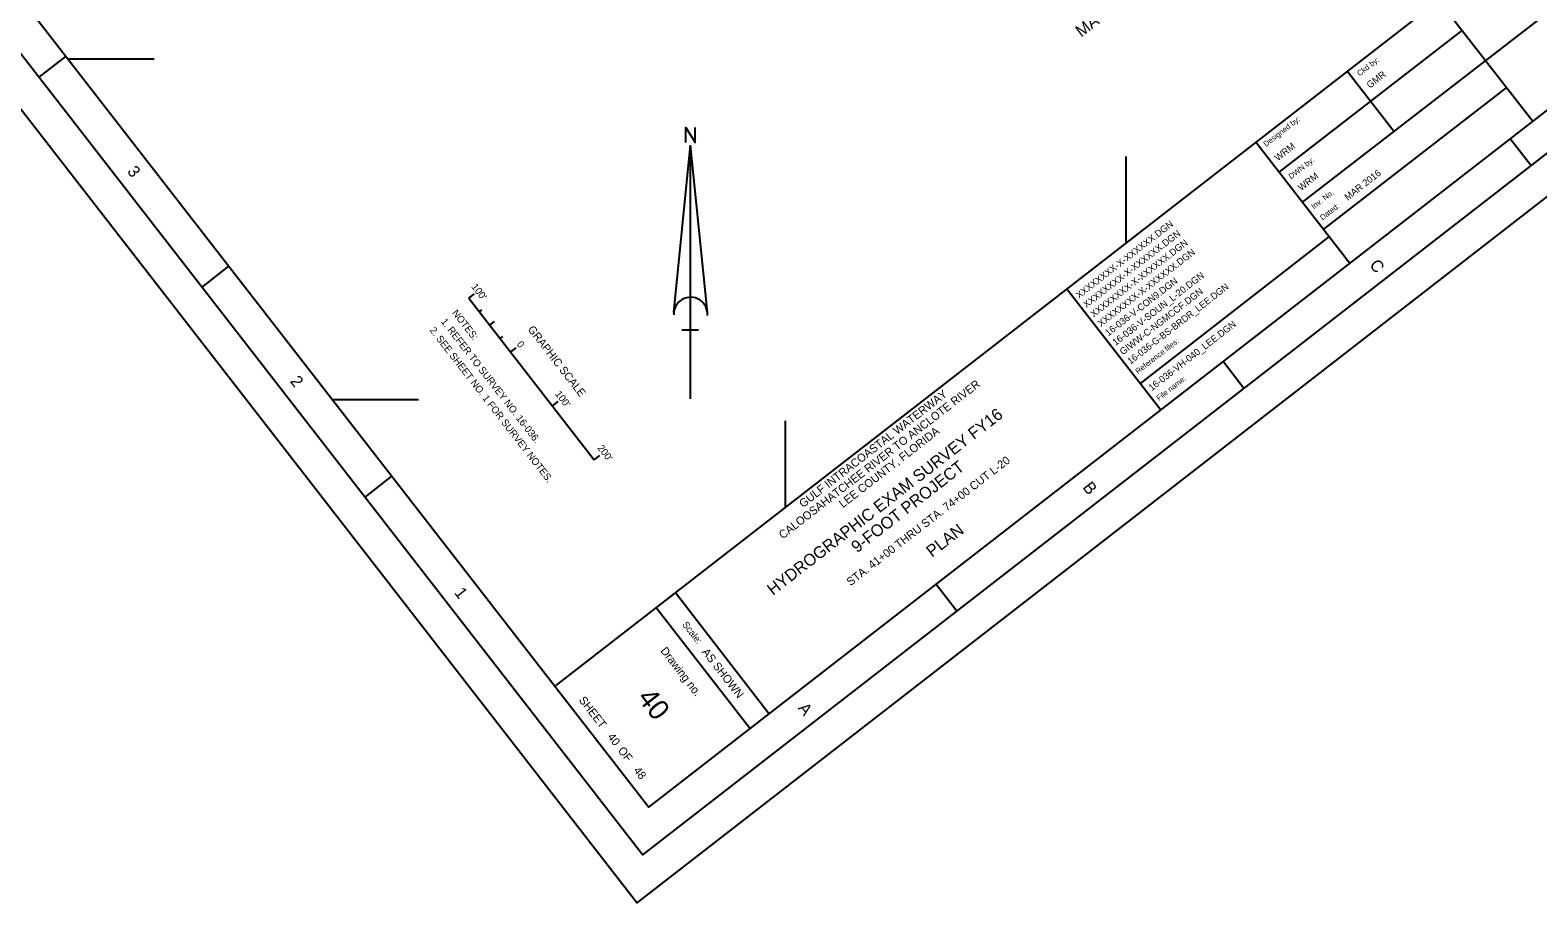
# Model space of a CAD drawing. Extents: x 575584 to 580968, y 857761 to 863322.
# Drawn here: x 577392 to 579604, y 857761 to 859042 of the extents above; entities that cross this region are included whole.
import ezdxf

# ---------------------------------------------------------------- set-up
doc = ezdxf.new("R2010")
doc.units = 0
for name, color, linetype in [('G-ANNO-NPLT', 7, 'Continuous'), ('G-ANNO-TEXT-DRWG', 7, 'Continuous'), ('G-ANNO-TEXT-PROJ', 7, 'Continuous'), ('G-ANNO-TEXT-TTLB', 7, 'Continuous'), ('G-ANNO-TTLB', 7, 'Continuous'), ('V-ANNO-MATC-IDEN', 7, 'Continuous'), ('V-ANNO-NOTE', 7, 'Continuous'), ('V-ANNO-SYMB', 7, 'Continuous'), ('V-TOPO-COOR-STAT', 7, 'Continuous')]:
    doc.layers.add(name, color=color, linetype=linetype)

msp = doc.modelspace()

# ---------------------------------------------------------------- linework, layer by layer
at = {"layer": 'G-ANNO-NPLT'}
msp.add_lwpolyline([(578269.8, 863321.7), (580967.7, 859846), (578281.9, 857761.2), (575584, 861237)], close=True, dxfattribs=at)
msp.add_lwpolyline([(578321.5, 857791.8), (578282, 857761.1), (578251.3, 857800.6)], dxfattribs=at)
at = {"layer": 'G-ANNO-TTLB'}
for p, q in [((580689.4, 860041.4), (578161.6, 858079.3)), ((579258.8, 858789.3), (579938.3, 859315.9)), ((579458.1, 859086.6), (579596.5, 858908.2)), ((579224.6, 858833.6), (579493, 859041.6)), ((577404.7, 858972.8), (577444.2, 859003.5)), ((579323.9, 858982.5), (579393.1, 858893.4)), ((579557.9, 858958), (579289.6, 858749.7)), ((579189.5, 858878.7), (579328.2, 858700)), ((579594.1, 858843), (579563.4, 858882.5)), ((579298, 858738.9), (579020.4, 858523.4)), ((577643.9, 858664.7), (577683.4, 858695.4)), ((578912.7, 858662.2), (579050.6, 858484.5)), ((579172.8, 858516), (579142.1, 858555.5)), ((577883, 858356.7), (577922.5, 858387.3)), ((578751.5, 858189), (578720.9, 858228.5)), ((578338.4, 858216.5), (578476.3, 858038.7)), ((578310.2, 858194.6), (578448.2, 858016.8))]:
    msp.add_line(p, q, dxfattribs=at)
for points in [[(575654.1, 861228.1), (578290.7, 857831.4), (580897.6, 859854.8), (578260.9, 863251.6)], [(580827.4, 859863.6), (578298.1, 863122.2), (575770.3, 861160), (578299.6, 857901.5)]]:
    msp.add_lwpolyline(points, close=True, dxfattribs=at)
at = {"layer": 'V-ANNO-NOTE'}
for p, q in [((578035.4, 858648.5), (578043.7, 858654.9)), ((578035.4, 858648.5), (578219.4, 858411.5)), ((578050.7, 858628.8), (578054.5, 858631.7)), ((578066.1, 858609), (578072.8, 858614.2)), ((578081.4, 858589.3), (578085.2, 858592.2)), ((578096.7, 858569.5), (578105, 858575.9)), ((578096.7, 858569.5), (578105, 858575.9)), ((578096.7, 858569.5), (578100.7, 858572.6)), ((578158, 858490.5), (578166.3, 858496.9)), ((578219.4, 858411.5), (578227.6, 858417.9))]:
    msp.add_line(p, q, dxfattribs=at)
at = {"layer": 'V-ANNO-SYMB'}
for p, q in [((578336.1, 858627.6), (578360.8, 858873.3)), ((578360.8, 858501), (578360.8, 858873.3)), ((578385.5, 858627.6), (578360.8, 858873.3)), ((578372.5, 858601.6), (578347.7, 858601.6))]:
    msp.add_line(p, q, dxfattribs=at)
msp.add_lwpolyline([(578353.9, 858877.3), (578353.9, 858899.1), (578367.4, 858877.3), (578367.4, 858899.1)], dxfattribs=at)
msp.add_arc((578360.8, 858625.1), 24.8, 355.2984, 182.0673, dxfattribs=at)
at = {"layer": 'V-TOPO-COOR-STAT'}
for p, q in [((577446.9, 859000), (577573.5, 859000)), ((579000, 858730), (579000, 858856.6)), ((577835, 858500), (577961.6, 858500)), ((578500, 858341.9), (578500, 858468.5))]:
    msp.add_line(p, q, dxfattribs=at)

# ---------------------------------------------------------------- texts
at = {"layer": 'G-ANNO-TEXT-DRWG'}
for s, height, rotation, p in [('GMR', 10, 37.8192, (579357.5, 858956)), ('WRM', 10, 37.8192, (579222.5, 858849.3)), ('WRM', 10, 37.8192, (579256.8, 858805.5)), ('XXXXXXXX-X-XXXXXX.DGN', 10, 37.8192, (578930.9, 858647.5)), ('XXXXXXXX-X-XXXXXX.DGN', 10, 37.8192, (578941.6, 858633.7)), ('XXXXXXXX-X-XXXXXX.DGN', 10, 37.8192, (578952.3, 858619.9)), ('XXXXXXXX-X-XXXXXX.DGN', 10, 37.8192, (578963, 858606.1)), ('16-036-V-CON9.DGN', 10, 37.8192, (578973.8, 858592.2)), ('16-036-V-SOUN_L-20.DGN', 10, 37.8192, (578984.5, 858578.4)), ('GIWW-C-NGMCCF.DGN', 10, 37.8192, (578995.2, 858564.6)), ('16-036-VH-040_LEE.DGN', 10, 37.8192, (579037.6, 858511.8)), ('STA. 41+00 THRU STA. 74+00 CUT L-20', 12, 37.8192, (578595.5, 858225.7)), ('PLAN', 17.5, 37.8192, (578715.1, 858267.6)), ('40', 30, 307.8192, (578281.4, 858061.6)), (' 40          48', 12, 307.8192, (578235.3, 858008))]:
    msp.add_text(s, height=height, rotation=rotation, dxfattribs=at).set_placement(p)
at = {"layer": 'G-ANNO-TEXT-PROJ'}
for s, height, p in [('MAR 2016', 10, (579325, 858791.5)), ('16-036-G-BS-BRDR_LEE.DGN', 9.8, (579006.4, 858550.9)), ('CALOOSAHATCHEE RIVER TO ANCLOTE RIVER', 12, (578496, 858294.5)), ('GULF INTRACOASTAL WATERWAY', 12, (578525.8, 858340.4)), ('HYDROGRAPHIC EXAM SURVEY FY16', 17.5, (578481.6, 858211.5)), ('LEE COUNTY, FLORIDA', 12, (578584.2, 858340.2)), ('9-FOOT PROJECT', 17.5, (578605, 858274))]:
    msp.add_text(s, height=height, rotation=37.8192, dxfattribs=at).set_placement(p)
at = {"layer": 'G-ANNO-TEXT-TTLB'}
for s, height, rotation, p in [('Ckd by:', 8, 37.8192, (579342.5, 858974)), ('Designed by:', 8, 37.8192, (579205.1, 858870.4)), ('DWN by:', 8, 37.8192, (579242, 858822.9)), ('Inv. No.', 8, 37.8192, (579275.3, 858778.8)), ('Dated:', 8, 37.8192, (579288.1, 858762.4)), ('Reference files:', 8, 37.8192, (579017.3, 858537)), ('File name:', 8, 37.8192, (579048.1, 858497.6)), ('Scale:', 10, 307.8192, (578347.9, 858169.3)), ('Drawing no.', 12, 307.8192, (578315.8, 858130.8)), ('AS SHOWN', 12, 307.8192, (578376.7, 858129.1)), ('SHEET         OF', 12, 307.8192, (578196, 858058.5))]:
    msp.add_text(s, height=height, rotation=rotation, dxfattribs=at).set_placement(p)
at = {"layer": 'G-ANNO-TTLB'}
for s, p in [('3', (577533.2, 858834.4)), ('C', (579356.1, 858697.2)), ('2', (577772.2, 858526.5)), ('B', (578935.3, 858370.8)), ('1', (578013.3, 858215.9)), ('A', (578517.6, 858046.6))]:
    msp.add_text(s, height=17.5, rotation=307.8192, dxfattribs=at).set_placement(p)
at = {"layer": 'V-ANNO-MATC-IDEN'}
msp.add_text('MATCHLINE SHEET NO. 039 LEE STA. 41+00', height=17.52, rotation=37.8192, dxfattribs=at).set_placement((578934.1, 859030.9))
at = {"layer": 'V-ANNO-NOTE'}
for s, height, p in [("100'", 10.42, (578038.5, 858665.2)), ('NOTES:', 10.42, (578010.2, 858626.7)), ('2. SEE SHEET NO. 1 FOR SURVEY NOTES.', 10.416, (577977.3, 858601.2)), ('1. REFER TO SURVEY NO. 16-036.', 10.416, (577993.8, 858614)), ('GRAPHIC SCALE', 11.666, (578121.1, 858602.6)), ('0', 10.4, (578105, 858580.7)), ("100'", 10.42, (578161.3, 858507.8)), ("200'", 10.42, (578223.3, 858428.6))]:
    msp.add_text(s, height=height, rotation=307.8192, dxfattribs=at).set_placement(p)

doc.saveas('drawing.dxf')
